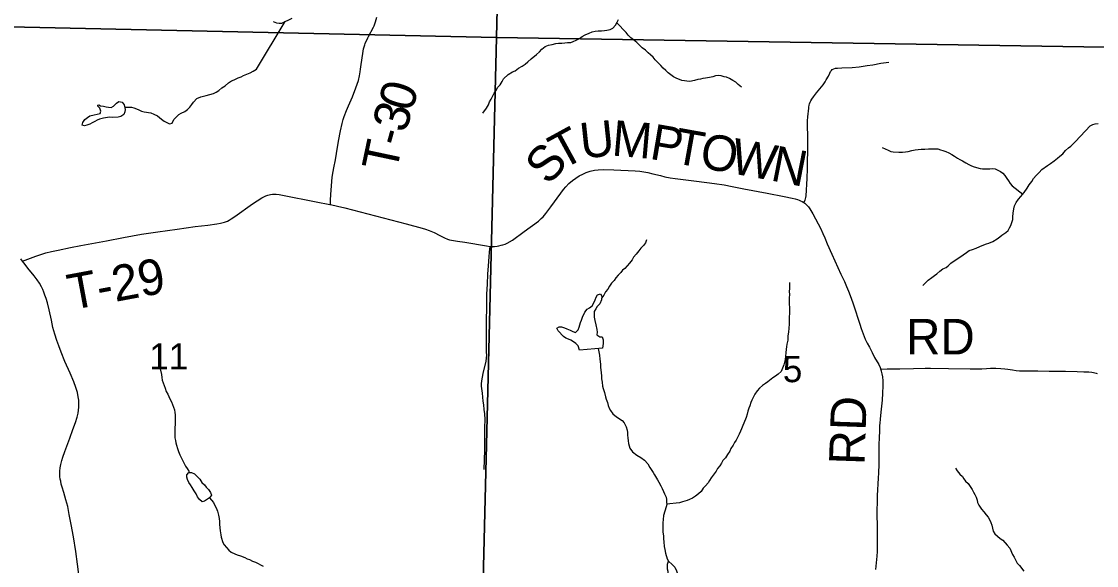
# Model space of a CAD drawing. Extents: x -7.9 to 76.1, y 0 to 22.
# Drawn here: x 3.631 to 5.35, y 16.568 to 17.437 of the extents above; entities that cross this region are included whole.
import ezdxf

# ---------------------------------------------------------------- set-up
doc = ezdxf.new("R2010")
doc.units = 0
for name, color, linetype in [('GM_X_Minor_River', 7, 'Continuous'), ('GM_X_Section', 7, 'Continuous'), ('GM_X_Section_Text', 7, 'Continuous'), ('GM_X_State_Route', 7, 'Continuous'), ('GM_X_Township_Road', 7, 'Continuous'), ('GM_X_Township_Road_Text', 7, 'Continuous')]:
    doc.layers.add(name, color=color, linetype=linetype)

msp = doc.modelspace()

# ---------------------------------------------------------------- linework, layer by layer
at = {"layer": 'GM_X_Minor_River'}
for points in [[(3.7963, 17.3003), (3.8071, 17.3003), (3.8112, 17.2992), (3.8154, 17.2978), (3.8192, 17.2959), (3.8234, 17.2941), (3.8276, 17.293), (3.8382, 17.291), (3.8432, 17.2891), (3.8489, 17.2862), (3.8551, 17.281), (3.8593, 17.278), (3.8635, 17.2755), (3.8681, 17.2736), (3.8722, 17.2745), (3.8751, 17.2806), (3.8785, 17.2844), (3.8829, 17.2883), (3.8867, 17.2907), (3.8923, 17.2934), (3.8968, 17.2965), (3.9005, 17.3004), (3.9039, 17.3043), (3.9064, 17.3081), (3.9116, 17.3139), (3.918, 17.317), (3.9222, 17.3179), (3.9267, 17.3191), (3.9327, 17.3203), (3.9383, 17.3223), (3.9425, 17.3243), (3.947, 17.327), (3.9518, 17.3309), (3.9571, 17.3344), (3.9623, 17.3391), (3.9671, 17.3422), (3.9716, 17.3438), (3.978, 17.3469), (3.9825, 17.3489), (3.9863, 17.3509), (3.9968, 17.3549), (4.0017, 17.3576), (4.0069, 17.3607), (4.0527, 17.437)], [(4.0339, 17.4371), (4.0393, 17.4349), (4.0435, 17.4343), (4.0476, 17.4347), (4.0641, 17.4422)], [(4.3692, 17.2904), (4.3747, 17.2985), (4.378, 17.3039), (4.3794, 17.3085), (4.3824, 17.3131), (4.3842, 17.3173), (4.3871, 17.3226), (4.3905, 17.3269), (4.3926, 17.3319), (4.3967, 17.3361), (4.4, 17.3415), (4.4019, 17.3453), (4.4093, 17.3523), (4.4164, 17.3566), (4.4209, 17.3582), (4.4261, 17.3624), (4.4321, 17.3656), (4.4366, 17.3687), (4.4411, 17.3726), (4.4463, 17.3776), (4.4545, 17.3846), (4.4594, 17.3888), (4.4631, 17.3927), (4.4687, 17.397), (4.4739, 17.3993), (4.48, 17.4006), (4.4856, 17.4022), (4.4901, 17.4027), (4.4951, 17.4027), (4.5, 17.4032), (4.5041, 17.4037), (4.5094, 17.4038), (4.5136, 17.405), (4.5181, 17.4073), (4.5233, 17.4097), (4.5278, 17.4132), (4.5323, 17.4159), (4.539, 17.4187), (4.5436, 17.4207), (4.5488, 17.4215), (4.5534, 17.422), (4.5587, 17.4221), (4.5636, 17.4226), (4.5673, 17.4234), (4.5726, 17.4242), (4.5768, 17.4262), (4.5812, 17.4312), (4.5838, 17.4362), (4.5856, 17.4404)], [(4.7824, 17.3323), (4.7774, 17.3364), (4.7732, 17.3401), (4.7689, 17.343), (4.7632, 17.346), (4.7586, 17.3482), (4.7548, 17.3489), (4.7499, 17.3503), (4.745, 17.3506), (4.7408, 17.3501), (4.7367, 17.3489), (4.7314, 17.3477), (4.725, 17.3464), (4.7208, 17.346), (4.7167, 17.3452), (4.7129, 17.3443), (4.7076, 17.3431), (4.7001, 17.3414), (4.6952, 17.3417), (4.6914, 17.3424), (4.6872, 17.3431), (4.6834, 17.3442), (4.6792, 17.346), (4.6739, 17.3486), (4.6654, 17.3553), (4.6616, 17.3586), (4.6573, 17.3627), (4.6535, 17.3668), (4.6489, 17.3717), (4.6446, 17.3758), (4.6411, 17.3803), (4.6369, 17.384), (4.6331, 17.387), (4.6288, 17.3914), (4.6238, 17.3951), (4.615, 17.4037), (4.61, 17.4078), (4.6054, 17.4111), (4.6015, 17.4153), (4.5981, 17.4197), (4.5831, 17.4349)], [(3.7969, 17.2967), (3.7966, 17.2929), (3.7948, 17.2883), (3.7903, 17.2852), (3.7858, 17.284), (3.7767, 17.2838), (3.7721, 17.2841), (3.7623, 17.2824), (3.7563, 17.2808), (3.7522, 17.2792), (3.7484, 17.2772), (3.7443, 17.2752), (3.7406, 17.2729), (3.736, 17.2713), (3.7323, 17.2705), (3.7285, 17.2716), (3.7292, 17.2757), (3.7325, 17.2804), (3.737, 17.2839), (3.7407, 17.2862), (3.7475, 17.2882), (3.7524, 17.2891), (3.7569, 17.2899), (3.7583, 17.2941), (3.7564, 17.2986), (3.7535, 17.3019), (3.7536, 17.3035), (3.7548, 17.3042), (3.7578, 17.3024), (3.7624, 17.3018), (3.7669, 17.3007), (3.7707, 17.3), (3.7745, 17.2997), (3.7786, 17.3017), (3.7831, 17.3067), (3.7872, 17.3094), (3.7922, 17.308), (3.7956, 17.3042), (3.7969, 17.2967)], [(5.3167, 17.2452), (5.3399, 17.2702), (5.344, 17.2725), (5.3482, 17.2737), (5.3527, 17.2742)], [(5.0722, 17.0151), (5.077, 17.0201), (5.0807, 17.0236), (5.0867, 17.0282), (5.0912, 17.0313), (5.0949, 17.0341), (5.0998, 17.0383), (5.1043, 17.0418), (5.1095, 17.0442), (5.1132, 17.0469), (5.117, 17.0511), (5.1226, 17.0547), (5.1282, 17.0586), (5.1368, 17.0644), (5.1424, 17.0679), (5.1465, 17.071), (5.1518, 17.073), (5.1578, 17.075), (5.1634, 17.0778), (5.1672, 17.079), (5.1743, 17.0818), (5.1781, 17.083), (5.1841, 17.0857), (5.1912, 17.09), (5.1953, 17.0928), (5.199, 17.0959), (5.205, 17.0998), (5.2091, 17.1032), (5.2109, 17.1075), (5.2131, 17.1113), (5.2146, 17.1159), (5.2164, 17.1205), (5.2163, 17.125), (5.217, 17.1307), (5.218, 17.138), (5.219, 17.1425), (5.2219, 17.1479), (5.2256, 17.1533), (5.2293, 17.1575), (5.2345, 17.1637), (5.2393, 17.1706), (5.2423, 17.1763), (5.2467, 17.1817), (5.2493, 17.1863), (5.2537, 17.1913), (5.2586, 17.196), (5.2626, 17.2006), (5.272, 17.2069), (5.2768, 17.2104), (5.2824, 17.2146), (5.2877, 17.2189), (5.2914, 17.222), (5.2962, 17.2259), (5.3003, 17.2309), (5.3055, 17.2352), (5.3093, 17.2379), (5.313, 17.2414), (5.3167, 17.2452)], [(5.0073, 17.236), (5.0123, 17.2334), (5.0169, 17.2316), (5.0211, 17.2294), (5.0249, 17.2291), (5.0343, 17.2285), (5.04, 17.2282), (5.0446, 17.2287), (5.0491, 17.2295), (5.0551, 17.2308), (5.06, 17.232), (5.0698, 17.2329), (5.0759, 17.233), (5.0816, 17.2335), (5.0918, 17.2337), (5.0963, 17.2334), (5.1005, 17.2323), (5.1043, 17.2312), (5.1092, 17.2294), (5.1142, 17.2272), (5.1188, 17.2247), (5.123, 17.2221), (5.128, 17.2188), (5.1318, 17.2165), (5.136, 17.2143), (5.141, 17.2114), (5.1459, 17.2088), (5.1501, 17.2066), (5.1543, 17.2048), (5.1642, 17.2023), (5.168, 17.2016), (5.1797, 17.2018), (5.1835, 17.2023), (5.1881, 17.2016), (5.1923, 17.1998), (5.1965, 17.1976), (5.2003, 17.1946), (5.2038, 17.1909), (5.2069, 17.1864), (5.2092, 17.1826), (5.2123, 17.1785), (5.215, 17.1747), (5.2324, 17.1611)], [(4.6308, 17.0885), (4.629, 17.0836), (4.6257, 17.0793), (4.6216, 17.0747), (4.6186, 17.0705), (4.6142, 17.0655), (4.6101, 17.0605), (4.6079, 17.0562), (4.6035, 17.0512), (4.5998, 17.0466), (4.596, 17.0427), (4.5923, 17.0396), (4.5897, 17.0358), (4.5853, 17.0316), (4.5816, 17.0273), (4.579, 17.0231), (4.5749, 17.0192), (4.5716, 17.0142), (4.5686, 17.0096), (4.5649, 17.005), (4.5624, 16.9996), (4.5594, 16.9958), (4.5592, 16.9954)], [(4.8594, 17.02), (4.8591, 17.0155), (4.8592, 17.0106), (4.8589, 17.0056), (4.859, 17.0007), (4.8587, 16.9954), (4.8592, 16.9699), (4.8589, 16.9658), (4.8586, 16.9597), (4.8587, 16.954), (4.8581, 16.9468), (4.8574, 16.9414), (4.8568, 16.9346), (4.8565, 16.9281), (4.8551, 16.9217), (4.8544, 16.9171), (4.8541, 16.9133), (4.8535, 16.9076), (4.8528, 16.9023), (4.8521, 16.8973), (4.8515, 16.8928), (4.8504, 16.8886), (4.8482, 16.8832), (4.8457, 16.8778), (4.8412, 16.8736), (4.8367, 16.8705), (4.8326, 16.8678), (4.8244, 16.8615), (4.8207, 16.8588), (4.8162, 16.8557), (4.8113, 16.8511), (4.8076, 16.8472), (4.8039, 16.8418), (4.8017, 16.8372), (4.7988, 16.8322), (4.7977, 16.8284), (4.7959, 16.8231), (4.7945, 16.8193), (4.7927, 16.8143), (4.7916, 16.8097), (4.7898, 16.8044), (4.7862, 16.7952), (4.7844, 16.7914), (4.7826, 16.7864), (4.7808, 16.7826), (4.779, 16.778), (4.7764, 16.7734), (4.7742, 16.7684), (4.7712, 16.7646), (4.7691, 16.76), (4.7657, 16.7546), (4.7639, 16.7508), (4.7602, 16.7454), (4.7569, 16.7401), (4.7528, 16.7358), (4.7506, 16.7316), (4.7477, 16.727), (4.7444, 16.7228), (4.7422, 16.7189), (4.7374, 16.712), (4.734, 16.7078), (4.7314, 16.7039), (4.7292, 16.7001), (4.7252, 16.6951), (4.7214, 16.6916), (4.7178, 16.6859), (4.7137, 16.6824), (4.7092, 16.6785), (4.7043, 16.6754), (4.6994, 16.6734), (4.6957, 16.6718), (4.6882, 16.6694), (4.6836, 16.6678), (4.6628, 16.6661)], [(4.5236, 16.9122), (4.5214, 16.9188), (4.5176, 16.9226), (4.5137, 16.9255), (4.5099, 16.9277), (4.5061, 16.9296), (4.5019, 16.9314), (4.4981, 16.9336), (4.4896, 16.9426), (4.4872, 16.9471), (4.491, 16.9491), (4.4948, 16.9491), (4.4997, 16.9477), (4.5035, 16.9462), (4.5085, 16.9437), (4.5131, 16.9418), (4.5173, 16.9404), (4.5213, 16.9446), (4.5232, 16.9489), (4.5253, 16.9561), (4.5267, 16.9599), (4.5282, 16.9645), (4.5322, 16.9729), (4.5359, 16.9775), (4.5396, 16.9795), (4.5438, 16.9826), (4.5463, 16.9876), (4.5485, 16.9926), (4.5499, 16.9968), (4.5525, 17.0006), (4.557, 17.0022), (4.5594, 16.9985), (4.5587, 16.9924), (4.5558, 16.9859), (4.5517, 16.982), (4.5495, 16.9782), (4.5469, 16.9739), (4.5467, 16.9682), (4.5471, 16.9645), (4.548, 16.9592), (4.5496, 16.9524), (4.5512, 16.9448), (4.5517, 16.9406), (4.5514, 16.9364), (4.556, 16.9335), (4.5598, 16.9332), (4.5614, 16.9283), (4.5611, 16.9226), (4.5608, 16.9188), (4.5601, 16.915), (4.5236, 16.9122)], [(4.5534, 16.9145), (4.5554, 16.9039), (4.5562, 16.8974), (4.5571, 16.8895), (4.5572, 16.8846), (4.5581, 16.8758), (4.5586, 16.8709), (4.5587, 16.866), (4.5595, 16.8607), (4.5604, 16.8542), (4.5616, 16.8505), (4.5636, 16.8444), (4.5649, 16.8376), (4.5661, 16.8339), (4.5681, 16.8282), (4.5693, 16.8233), (4.5712, 16.8191), (4.5732, 16.8154), (4.5767, 16.8101), (4.5828, 16.8057), (4.5916, 16.7998), (4.5947, 16.796), (4.5983, 16.7893), (4.5995, 16.7843), (4.6003, 16.7802), (4.6004, 16.7764), (4.6008, 16.7718), (4.6013, 16.7669), (4.6018, 16.7628), (4.6038, 16.7556), (4.608, 16.7496), (4.6153, 16.7444), (4.6218, 16.7403), (4.6272, 16.7363), (4.6326, 16.7303), (4.6361, 16.7246), (4.6412, 16.7164), (4.6435, 16.7126), (4.6482, 16.7048), (4.6501, 16.701), (4.6537, 16.695), (4.6556, 16.6908), (4.658, 16.686), (4.6596, 16.6822), (4.6619, 16.6769), (4.6627, 16.6731), (4.6624, 16.6693), (4.6629, 16.6652), (4.6622, 16.6614), (4.6597, 16.6545), (4.6579, 16.6476), (4.6572, 16.6412), (4.657, 16.6362), (4.6567, 16.6294), (4.6568, 16.6214), (4.6577, 16.6154), (4.6578, 16.6104), (4.6582, 16.6059), (4.6591, 16.5983), (4.66, 16.5934), (4.6608, 16.5874), (4.6636, 16.5787), (4.6656, 16.5749)], [(3.8522, 16.8896), (3.8526, 16.8843), (3.8551, 16.873), (3.8556, 16.8681), (3.8564, 16.8643), (3.858, 16.8598), (3.8596, 16.8556), (3.8608, 16.8515), (3.8628, 16.8458), (3.8651, 16.8417), (3.8667, 16.8379), (3.869, 16.8334), (3.8714, 16.8296), (3.873, 16.8251), (3.8758, 16.8164), (3.8766, 16.8123), (3.8771, 16.8085), (3.8772, 16.799), (3.8769, 16.7952), (3.8763, 16.7861), (3.8766, 16.772), (3.8774, 16.7679), (3.8782, 16.7641), (3.8794, 16.7603), (3.8806, 16.755), (3.8822, 16.7501), (3.8846, 16.7445), (3.887, 16.7392), (3.8893, 16.7351), (3.8936, 16.7268), (3.8963, 16.7231), (3.8987, 16.7189), (3.8995, 16.7166)], [(5.1246, 16.7234), (5.1274, 16.7192), (5.1316, 16.714), (5.1358, 16.7103), (5.1382, 16.7065), (5.1409, 16.7028), (5.1447, 16.699), (5.1482, 16.6942), (5.1514, 16.6893), (5.1537, 16.6852), (5.1557, 16.6814), (5.1576, 16.6769), (5.1592, 16.6724), (5.16, 16.6686), (5.162, 16.6641), (5.1663, 16.6581), (5.1701, 16.6536), (5.1736, 16.6491), (5.1767, 16.6453), (5.1791, 16.6412), (5.1814, 16.6367), (5.183, 16.6322), (5.1839, 16.6273), (5.1851, 16.6227), (5.1878, 16.6186), (5.1959, 16.6108), (5.2001, 16.6082), (5.2074, 16.6004), (5.2113, 16.5955), (5.2156, 16.5857), (5.2183, 16.5812), (5.2231, 16.5714), (5.2269, 16.5681), (5.2339, 16.5591)], [(3.932, 16.6759), (3.9237, 16.6708), (3.92, 16.6696), (3.9158, 16.6733), (3.9127, 16.6774), (3.9107, 16.6823), (3.9072, 16.6872), (3.9044, 16.6925), (3.9014, 16.6966), (3.899, 16.7007), (3.897, 16.7052), (3.8955, 16.709), (3.8958, 16.7128), (3.8987, 16.7167), (3.9029, 16.7164), (3.9079, 16.7142), (3.9125, 16.7097), (3.9163, 16.7056), (3.9198, 16.7007), (3.9237, 16.697), (3.9268, 16.6932), (3.9302, 16.6891), (3.9333, 16.6846), (3.9349, 16.6801), (3.932, 16.6759)], [(3.9321, 16.6761), (3.9385, 16.6688), (3.9405, 16.6639), (3.9425, 16.6601), (3.9445, 16.6545), (3.9465, 16.6484), (3.9473, 16.6428), (3.9478, 16.6382), (3.9479, 16.634), (3.9483, 16.628), (3.9488, 16.6234), (3.9501, 16.617), (3.9505, 16.6132), (3.9533, 16.6046), (3.9556, 16.6008), (3.9591, 16.5967), (3.963, 16.5926), (3.9668, 16.5892), (3.9722, 16.5867), (3.9763, 16.5848), (3.9813, 16.5834), (3.9882, 16.5805), (3.992, 16.5787), (3.9958, 16.5776), (4.0007, 16.575), (4.0057, 16.5732), (4.0095, 16.571), (4.0137, 16.5688), (4.0175, 16.567)], [(4.6656, 16.5749), (4.6718, 16.5693), (4.676, 16.5652), (4.6787, 16.5592), (4.6816, 16.5494), (4.6824, 16.5452), (4.6829, 16.5407), (4.6818, 16.5354), (4.68, 16.5315), (4.6758, 16.5315), (4.6712, 16.5344), (4.6693, 16.5386), (4.6673, 16.5442), (4.6661, 16.5491), (4.6651, 16.5582), (4.6643, 16.562), (4.6641, 16.5702), (4.6656, 16.5749)]]:
    msp.add_lwpolyline(points, dxfattribs=at)
at = {"layer": 'GM_X_Section'}
for points in [[(3.389, 18.2623), (4.4107, 18.2442), (4.3909, 17.4116), (3.3681, 17.4339)], [(4.4107, 18.2442), (5.4207, 18.223), (5.3971, 17.3953), (4.3909, 17.4116)], [(4.3909, 17.4116), (4.3656, 16.3922), (3.3491, 16.4191), (3.3681, 17.4339)], [(5.3971, 17.3953), (5.3953, 17.2709), (5.3702, 16.3705), (4.3656, 16.3922), (4.3909, 17.4116)]]:
    msp.add_lwpolyline(points, close=True, dxfattribs=at)
at = {"layer": 'GM_X_State_Route'}
msp.add_lwpolyline([(3.7236, 16.5494), (3.7209, 16.5698), (3.718, 16.5901), (3.7144, 16.6135), (3.7108, 16.6335), (3.7078, 16.6494), (3.7053, 16.662), (3.7023, 16.6728), (3.699, 16.6846), (3.6963, 16.6933), (3.695, 16.6977), (3.694, 16.7024), (3.6934, 16.7059), (3.6929, 16.7103), (3.6928, 16.7136), (3.6929, 16.7185), (3.6932, 16.7241), (3.694, 16.7293), (3.6958, 16.7358), (3.6974, 16.7409), (3.7008, 16.7502), (3.7087, 16.7713), (3.7137, 16.7852), (3.7179, 16.7966), (3.7202, 16.805), (3.7217, 16.8114), (3.7224, 16.8161), (3.723, 16.8211), (3.7231, 16.8258), (3.7228, 16.8323), (3.7222, 16.8375), (3.7209, 16.8441), (3.7181, 16.8524), (3.7148, 16.8615), (3.709, 16.8754), (3.7009, 16.8941), (3.6948, 16.9087), (3.6909, 16.9187), (3.6878, 16.9274), (3.6846, 16.9375), (3.6816, 16.9483), (3.6791, 16.9598), (3.6754, 16.9763), (3.6728, 16.9878), (3.6709, 16.9943), (3.6689, 17), (3.6672, 17.0049), (3.6653, 17.0091), (3.6635, 17.0132), (3.66, 17.0191), (3.6566, 17.0246), (3.6515, 17.031), (3.6415, 17.0429), (3.6372, 17.0486), (3.6329, 17.0542), (3.6305, 17.0581)], dxfattribs=at)
at = {"layer": 'GM_X_Township_Road'}
for points in [[(4.1254, 17.1446), (4.1255, 17.1519), (4.126, 17.1609), (4.1268, 17.1744), (4.1283, 17.1886), (4.1295, 17.1974), (4.1308, 17.2034), (4.1333, 17.2162), (4.1351, 17.2262), (4.1379, 17.2429), (4.1403, 17.2572), (4.1413, 17.2625), (4.144, 17.274), (4.1457, 17.2807), (4.1472, 17.2855), (4.1508, 17.2947), (4.1542, 17.3022), (4.1606, 17.3169), (4.166, 17.331), (4.1682, 17.3372), (4.17, 17.3429), (4.1718, 17.3503), (4.173, 17.3569), (4.1736, 17.3607), (4.1744, 17.3684), (4.1769, 17.386), (4.1784, 17.3933), (4.1803, 17.3999), (4.181, 17.4019), (4.185, 17.4112), (4.1861, 17.4133), (4.1942, 17.428), (4.1951, 17.4301), (4.1974, 17.4367), (4.1997, 17.4441)], [(4.8823, 17.1477), (4.8842, 17.1518), (4.8848, 17.1539), (4.8854, 17.156), (4.8858, 17.1586), (4.8876, 17.1865), (4.8881, 17.2023), (4.8888, 17.241), (4.8886, 17.25), (4.888, 17.2742), (4.8882, 17.2785), (4.8887, 17.2849), (4.89, 17.2986), (4.8902, 17.3002), (4.8907, 17.3032), (4.8913, 17.3056), (4.8923, 17.3081), (4.8934, 17.3104), (4.8949, 17.3129), (4.8976, 17.3168), (4.9025, 17.323), (4.9131, 17.3359), (4.9161, 17.3406), (4.9181, 17.3441), (4.9216, 17.3499), (4.9238, 17.3543), (4.925, 17.3571), (4.9262, 17.3589), (4.9276, 17.3604), (4.9299, 17.3616), (4.933, 17.3623), (4.9358, 17.3626), (4.943, 17.3629), (4.9593, 17.3638), (4.9709, 17.3649), (4.9833, 17.3666), (4.9927, 17.3681), (5.0055, 17.3703), (5.0179, 17.3723)], [(4.1245, 17.1448), (4.1254, 17.1446), (4.1364, 17.1423), (4.1485, 17.1395), (4.1851, 17.1296), (4.2463, 17.1137), (4.2717, 17.1068), (4.2775, 17.1051), (4.2834, 17.103), (4.2911, 17.0998), (4.3001, 17.0952), (4.3044, 17.0929), (4.3079, 17.0913), (4.3122, 17.0895), (4.3159, 17.0885), (4.3284, 17.0861), (4.3401, 17.0844), (4.3746, 17.0786), (4.3807, 17.0778), (4.3826, 17.0777), (4.3878, 17.0778), (4.3918, 17.0782), (4.3944, 17.0786), (4.3985, 17.0795), (4.4011, 17.0802), (4.4045, 17.0813), (4.4079, 17.0829), (4.4162, 17.0879), (4.4353, 17.1015), (4.4578, 17.1183), (4.4623, 17.1221), (4.4652, 17.1248), (4.4698, 17.1303), (4.4777, 17.1409), (4.4936, 17.1628), (4.4977, 17.1685), (4.5014, 17.1728), (4.5066, 17.178), (4.5124, 17.183), (4.5177, 17.187), (4.5231, 17.1903), (4.5287, 17.1931), (4.5342, 17.1959), (4.5404, 17.1979), (4.5473, 17.1996), (4.5531, 17.2002), (4.5621, 17.2005), (4.5782, 17.2002), (4.6123, 17.1987), (4.6201, 17.1979), (4.6263, 17.197), (4.6328, 17.1957), (4.6409, 17.1939), (4.6528, 17.1908), (4.6601, 17.1891), (4.6684, 17.1875), (4.6766, 17.1862), (4.7108, 17.182), (4.7395, 17.1785), (4.7548, 17.1761), (4.7677, 17.1737), (4.7861, 17.17), (4.8234, 17.1627), (4.8507, 17.1574), (4.8635, 17.1548), (4.8684, 17.1537), (4.8719, 17.1527), (4.8748, 17.1516), (4.8768, 17.1508), (4.8794, 17.1495), (4.8823, 17.1477), (4.8836, 17.1468), (4.8871, 17.1438), (4.8897, 17.1409), (4.892, 17.1379), (4.8966, 17.1298), (4.905, 17.114), (4.9086, 17.1067), (4.9125, 17.0983), (4.9156, 17.0912), (4.9195, 17.0819), (4.9269, 17.0651), (4.9412, 17.0335), (4.9471, 17.0215), (4.9504, 17.0137), (4.9538, 17.006), (4.9579, 16.9952), (4.9611, 16.986), (4.9647, 16.9748), (4.9684, 16.9633), (4.9717, 16.9533), (4.9739, 16.9464), (4.9772, 16.9379), (4.9804, 16.9296), (4.9835, 16.9231), (4.987, 16.9166), (4.9913, 16.9084), (4.9954, 16.9004), (5.002, 16.8888), (5.0041, 16.8844), (5.0053, 16.8814), (5.0153, 16.882), (5.0356, 16.8824), (5.0575, 16.8828), (5.0763, 16.8831), (5.0847, 16.8832), (5.1136, 16.8829), (5.1483, 16.8819), (5.167, 16.882), (5.1742, 16.8826), (5.1805, 16.8833), (5.1852, 16.8834), (5.189, 16.8834), (5.1973, 16.8828), (5.2035, 16.8823), (5.2082, 16.8816), (5.216, 16.8804), (5.2216, 16.8797), (5.2269, 16.8792), (5.2328, 16.879), (5.2565, 16.8788), (5.2743, 16.8786), (5.3003, 16.8782), (5.3193, 16.8778), (5.3299, 16.8774), (5.3378, 16.8772), (5.3428, 16.8768), (5.3452, 16.8765), (5.3472, 16.876), (5.3494, 16.8753), (5.3513, 16.8745)], [(3.6329, 17.0542), (3.6542, 17.0623), (3.67, 17.0674), (3.6792, 17.0698), (3.6899, 17.072), (3.7098, 17.076), (3.7262, 17.079), (3.767, 17.0864), (3.7946, 17.0922), (3.8232, 17.0973), (3.8494, 17.101), (3.8802, 17.1052), (3.9092, 17.1093), (3.9293, 17.1119), (3.9435, 17.114), (3.9496, 17.115), (3.9558, 17.1166), (3.9605, 17.1182), (3.9634, 17.1197), (3.9668, 17.1217), (3.9725, 17.1255), (4.0007, 17.1459), (4.0155, 17.1555), (4.0187, 17.1572), (4.0219, 17.1585), (4.0251, 17.1596), (4.0295, 17.1606), (4.0329, 17.161), (4.0387, 17.1612), (4.0432, 17.1606), (4.0487, 17.1597), (4.1024, 17.1491), (4.1245, 17.1448)], [(4.3713, 16.7211), (4.3722, 16.7521), (4.3724, 16.7884), (4.3725, 16.8012), (4.372, 16.81), (4.3713, 16.8169), (4.3706, 16.8246), (4.3696, 16.8307), (4.3683, 16.843), (4.3668, 16.8544), (4.3666, 16.858), (4.3672, 16.8631), (4.3695, 16.8748), (4.3741, 16.8946), (4.3749, 16.8993), (4.3752, 16.904), (4.3749, 16.9088), (4.3746, 16.9163), (4.3748, 16.9429), (4.3749, 16.9635), (4.3752, 16.9761), (4.3753, 16.9864), (4.3754, 16.9961), (4.3756, 17.0017), (4.3764, 17.0176), (4.3772, 17.0335), (4.3779, 17.0468), (4.3789, 17.0611), (4.3796, 17.0688), (4.3807, 17.0778)], [(4.9974, 16.5617), (4.9991, 16.5774), (4.9994, 16.583), (4.9998, 16.5904), (4.9999, 16.6255), (4.9994, 16.6546), (4.9998, 16.6706), (4.9999, 16.6797), (5.0016, 16.7074), (5.002, 16.7158), (5.0024, 16.7295), (5.0026, 16.7605), (5.003, 16.7722), (5.0035, 16.7825), (5.0039, 16.7917), (5.0042, 16.7955), (5.0046, 16.8015), (5.0056, 16.8127), (5.0078, 16.8319), (5.0087, 16.8435), (5.0092, 16.8549), (5.0089, 16.8629), (5.0083, 16.8694), (5.0074, 16.874), (5.0065, 16.8785), (5.0053, 16.8814)]]:
    msp.add_lwpolyline(points, dxfattribs=at)

# ---------------------------------------------------------------- texts
at = {"layer": 'GM_X_Section_Text'}
for s, height, p in [('11', 0.04186, (3.8357, 16.8811)), ('5', 0.0419, (4.8486, 16.8608))]:
    msp.add_text(s, height=height, rotation=0, dxfattribs=at).set_placement(p)
at = {"layer": 'GM_X_Township_Road_Text'}
for s, height, rotation, p in [('0', 0.0568, 73.4627, (4.2553, 17.2911)), ('3', 0.0568, 73.695, (4.2455, 17.2575)), ('U', 0.0568, 6.0876, (4.527, 17.2178)), ('M', 0.0568, 355.0762, (4.5739, 17.2231)), ('-', 0.0568, 74.5285, (4.2393, 17.2352)), ('T', 0.0568, 28.7083, (4.4954, 17.1991)), ('P', 0.0568, 350.3033, (4.6341, 17.2179)), ('T', 0.0568, 349.8021, (4.6717, 17.2115)), ('O', 0.0568, 349.801, (4.7136, 17.204)), ('T', 0.0568, 78.0294, (4.2307, 17.1946)), ('S', 0.0568, 48.402, (4.474, 17.1737)), ('W', 0.0568, 349.7954, (4.7628, 17.1951)), ('N', 0.0568, 348.9301, (4.8273, 17.1835)), ('T-29', 0.05682, 10.5786, (3.7108, 16.9759)), ('RD', 0.05682, 0, (5.0457, 16.9051)), ('RD', 0.05682, 88.0273, (4.9791, 16.7279))]:
    msp.add_text(s, height=height, rotation=rotation, dxfattribs=at).set_placement(p)

doc.saveas('drawing.dxf')
